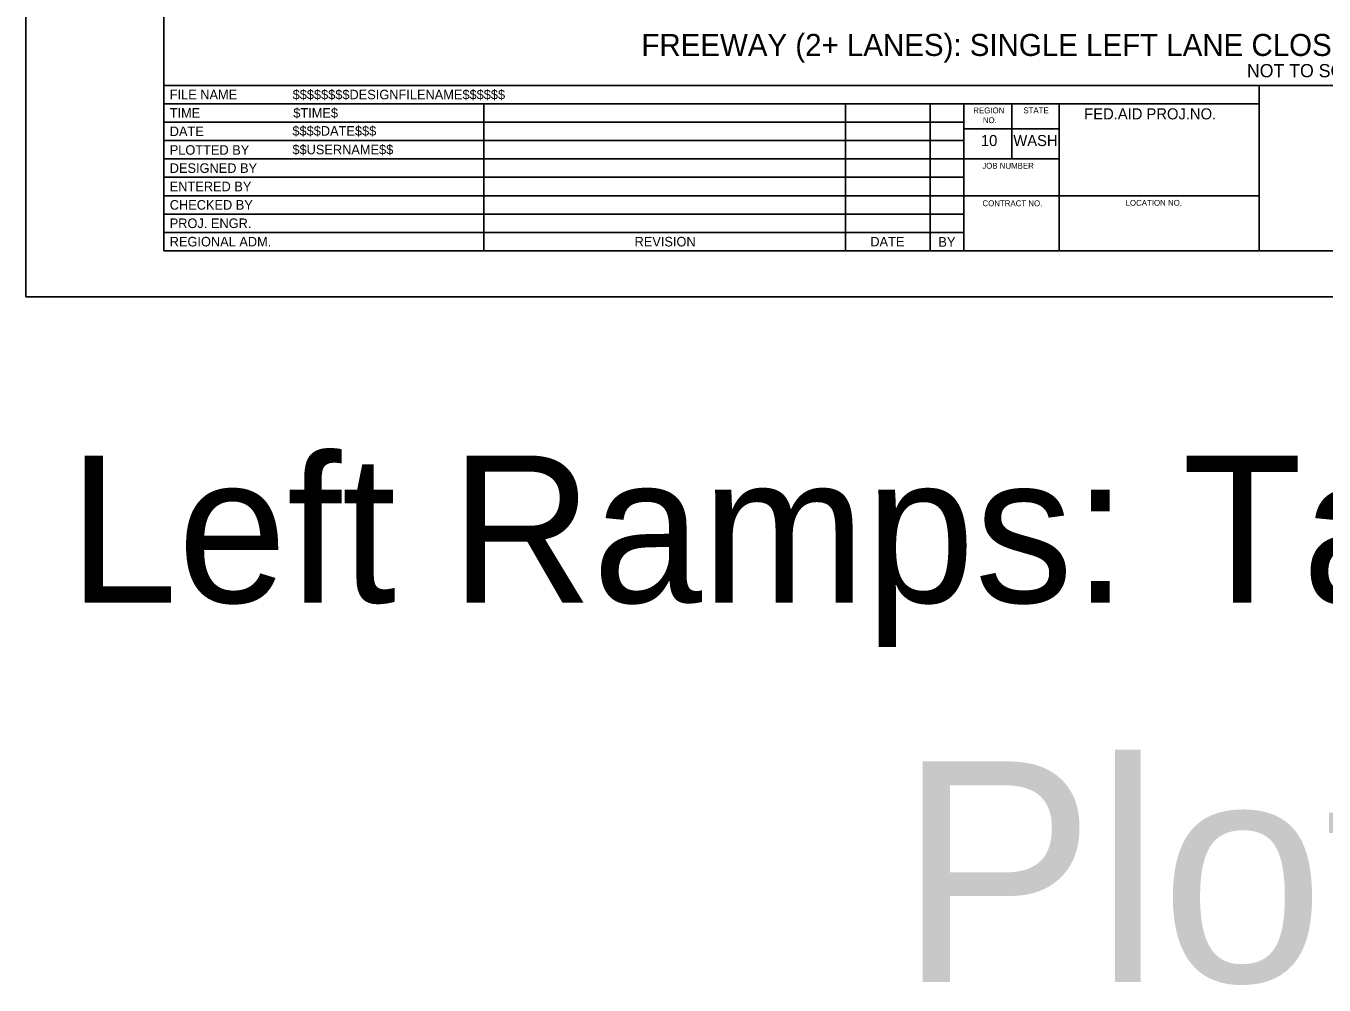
# Model space of a CAD drawing. Extents: x 99999 to 100116, y 99995 to 100013.
# Drawn here: x 100079.06 to 100087.9, y 99995.01 to 100001.53 of the extents above; entities that cross this region are included whole.
import ezdxf

# ---------------------------------------------------------------- set-up
doc = ezdxf.new("R2010")
doc.units = 0
for name, color, linetype in [('SH_DE_DetailHeading1Text', 7, 'Continuous'), ('SH_GI_PlotLimits', 7, 'Continuous'), ('SH_GI_SheetBorder', 7, 'Continuous'), ('SH_GI_SheetLocationText', 7, 'Continuous'), ('SH_GI_SheetTextInCells', 7, 'Continuous'), ('SH_GI_TitleBlockText', 7, 'Continuous')]:
    doc.layers.add(name, color=color, linetype=linetype)

msp = doc.modelspace()

# ---------------------------------------------------------------- linework, layer by layer
at = {"layer": 'SH_GI_PlotLimits'}
msp.add_lwpolyline([(100079.0625, 99999.6875), (100096.0625, 99999.6875), (100096.0625, 100010.6875), (100079.0625, 100010.6875)], close=True, dxfattribs=at)
at = {"layer": 'SH_GI_SheetBorder'}
for p, q in [((100080, 100010.375), (100080, 100000)), ((100080, 100001.1259), (100095.75, 100001.1259)), ((100087.4566, 100000), (100087.4566, 100001.1259)), ((100080, 100001.0008), (100087.4566, 100001.0008)), ((100082.179, 100001.0008), (100082.179, 100000)), ((100084.641, 100001.0008), (100084.641, 100000)), ((100085.2164, 100001.0008), (100085.2164, 100000)), ((100085.4451, 100001.0008), (100085.4451, 100000)), ((100085.7719, 100000.6255), (100085.7719, 100001.0008)), ((100086.0956, 100000), (100086.0956, 100001.0008)), ((100080, 100000.8757), (100082.1821, 100000.8757)), ((100082.1821, 100000.8757), (100085.4466, 100000.8757)), ((100080, 100000.7506), (100082.1821, 100000.7506)), ((100082.1821, 100000.7506), (100085.4466, 100000.7506)), ((100086.0958, 100000.831), (100085.4466, 100000.831)), ((100080, 100000.6255), (100085.4466, 100000.6255)), ((100086.0958, 100000.6255), (100085.4466, 100000.6255)), ((100080, 100000.5004), (100085.4466, 100000.5004)), ((100080, 100000.3753), (100085.4466, 100000.3753)), ((100087.4566, 100000.3753), (100085.4466, 100000.3753)), ((100080, 100000.2502), (100085.4466, 100000.2502)), ((100080, 100000.1251), (100085.4466, 100000.1251)), ((100080, 100000), (100095.75, 100000))]:
    msp.add_line(p, q, dxfattribs=at)

# ---------------------------------------------------------------- texts
at = {"layer": 'SH_DE_DetailHeading1Text'}
for s, height, p in [('FREEWAY (2+ LANES): SINGLE LEFT LANE CLOSURE (MAINTAIN EXISTING SPEED LIMIT)', 0.15, (100083.2512, 100001.3259)), ('NOT TO SCALE', 0.09, (100087.3727, 100001.1809))]:
    msp.add_text(s, height=height, rotation=360, dxfattribs=at).set_placement(p)
at = {"layer": 'SH_GI_SheetLocationText'}
for s, height, p in [('Left Ramps: Tapered On-Ramp', 1, (100079.3513, 99997.6071)), ('Plot 5', 1.5, (100085.0007, 99995.0267))]:
    msp.add_text(s, height=height, dxfattribs=at).set_placement(p)
at = {"layer": 'SH_GI_SheetTextInCells'}
for s, height, p in [('FILE NAME', 0.06505, (100080.041, 100001.0308)), ('TIME', 0.06505, (100080.041, 100000.9057)), ('REGION', 0.04003, (100085.5099, 100000.9352)), ('STATE', 0.04003, (100085.8511, 100000.9357)), ('FED.AID PROJ.NO.', 0.07506, (100086.2652, 100000.8945)), ('DATE', 0.06505, (100080.041, 100000.7806)), ('NO.', 0.04003, (100085.5752, 100000.869)), ('10', 0.07506, (100085.5621, 100000.7131)), ('WASH', 0.07506, (100085.7826, 100000.7131)), ('PLOTTED BY', 0.06505, (100080.041, 100000.6538)), ('DESIGNED BY', 0.065052, (100080.041, 100000.5304)), ('JOB NUMBER', 0.04003, (100085.5712, 100000.5587)), ('ENTERED BY', 0.06505, (100080.041, 100000.4053)), ('CHECKED BY', 0.06505, (100080.041, 100000.2802)), ('CONTRACT NO.', 0.040032, (100085.5725, 100000.3037)), ('LOCATION NO.', 0.040032, (100086.5465, 100000.3067)), ('PROJ. ENGR.', 0.065052, (100080.041, 100000.1551)), ('REGIONAL ADM.', 0.065052, (100080.041, 100000.03)), ('REVISION', 0.06505, (100083.2048, 100000.03)), ('DATE', 0.06505, (100084.8091, 100000.03)), ('BY', 0.06505, (100085.2725, 100000.0285))]:
    msp.add_text(s, height=height, dxfattribs=at).set_placement(p)
at = {"layer": 'SH_GI_TitleBlockText'}
for s, height, p in [('$$$$$$$$DESIGNFILENAME$$$$$$', 0.065052, (100080.8775, 100001.0308)), ('$TIME$', 0.06505, (100080.882, 100000.9059)), ('$$$$DATE$$$', 0.065052, (100080.8759, 100000.7835)), ('$$USERNAME$$', 0.065052, (100080.8759, 100000.6567))]:
    msp.add_text(s, height=height, dxfattribs=at).set_placement(p)

doc.saveas('drawing.dxf')
